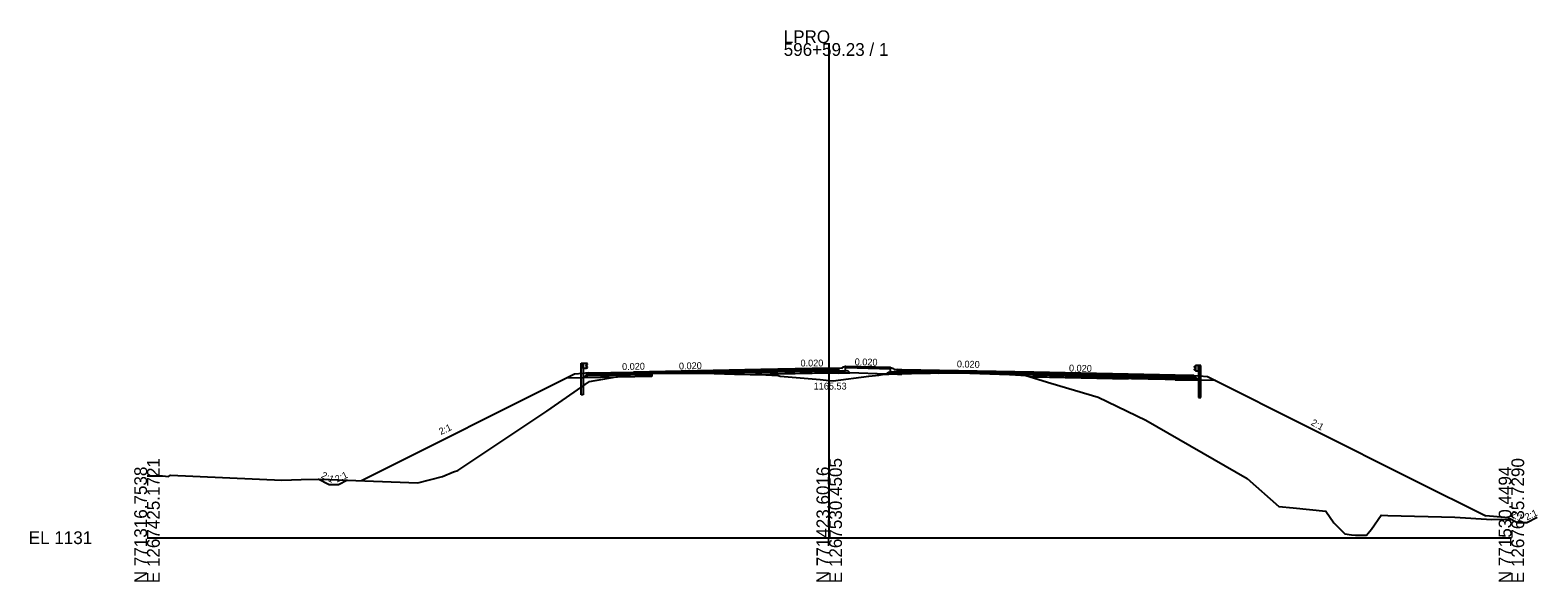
# Model space of a CAD drawing. Extents: x -3833 to 1267678, y -522 to 773248.
# Drawn here: x 4274.3 to 4605.8, y -9.7 to 111.5 of the extents above; entities that cross this region are included whole.
import ezdxf

# ---------------------------------------------------------------- set-up
doc = ezdxf.new("R2010")
doc.units = 0
for name, color, linetype in [('Exist Utilities Water UG Line SUE LOS B', 7, 'Continuous'), ('Prop Drainage Structure Catch Basin Grate 840 03E CELL', 7, 'Continuous'), ('Prop Drainage Structure Catch Basin Grate 840 03E Label', 7, 'Continuous'), ('Prop Drainage Structure Catch Basin Grate 840 03F CELL', 7, 'Continuous'), ('Prop Drainage Structure Catch Basin Grate 840 03F Label', 7, 'Continuous'), ('Prop Drainage Structure Catch Basin Grate 840 03G CELL', 7, 'Continuous'), ('Prop Drainage Structure Catch Basin Grate 840 03G Label', 7, 'Continuous'), ('Prop Drainage Structure Drop Inlet Grate 2 Narrow Slots and Flat Grates 840 29 CELL', 7, 'Continuous'), ('Prop Drainage Structure Drop Inlet Grate 2 Narrow Slots and Flat Grates 840 29 Label', 7, 'Continuous'), ('Prop Drainage Structure Headwall CELL', 7, 'Continuous'), ('Prop Drainage Structure Junction Box with Manhole CELL', 7, 'Continuous'), ('Prop Drainage Structure Junction Box with Manhole Label', 7, 'Continuous'), ('Prop Drainage Structure Junction Box with Manhole TB Label', 7, 'Continuous'), ('Prop Drainage Structure Pipe RCP 18in Class III', 7, 'Continuous'), ('Prop Drainage Structure Pipe RCP 18in Class III Label', 7, 'Continuous'), ('Prop Drainage Structure Pipe Removal', 7, 'Continuous'), ('Prop Drainage Structure Removal Label', 7, 'Continuous'), ('Prop Earthen Structure Ditch Flow Line', 7, 'Continuous'), ('Scratch_Level_3', 7, 'Continuous')]:
    doc.layers.add(name, color=color, linetype=linetype)

msp = doc.modelspace()

# ---------------------------------------------------------------- linework, layer by layer
at = {"layer": 'Prop Drainage Structure Catch Basin Grate 840 03F CELL'}
for p, q in [((4453.59, 37.62), (4453.68, 37.62)), ((4453.68, 37.62), (4463.49, 37.36)), ((4463.49, 37.36), (4463.49, 37.36)), ((4394, 35.93), (4347.15, 12.5)), ((4395.81, 36.07), (4394, 35.93)), ((4397, 36.17), (4395.81, 36.07)), ((4530.14, 35.63), (4531.33, 35.53)), ((4531.33, 35.53), (4533.14, 35.39)), ((4533.14, 35.39), (4578.79, 12.56)), ((4340.08, 11.62), (4337.63, 12.84)), ((4342.08, 11.62), (4340.08, 11.62)), ((4344.08, 12.62), (4342.08, 11.62)), ((4578.79, 12.56), (4594.36, 4.78)), ((4599.36, 4.36), (4594.36, 4.78)), ((4599.36, 4.36), (4601.36, 3.36)), ((4601.36, 3.36), (4603.36, 3.36)), ((4603.36, 3.36), (4605.65, 4.51))]:
    msp.add_line(p, q, dxfattribs=at)
at = {"layer": 'Prop Drainage Structure Catch Basin Grate 840 03F Label'}
for p, q in [((4435, 36.68), (4422.56, 36.43)), ((4435, 36.35), (4435, 36.68)), ((4435, 36.68), (4435, 36.68)), ((4465.98, 36.31), (4465.98, 36.64)), ((4465.98, 36.64), (4465.98, 36.64)), ((4465.98, 36.64), (4465.98, 36.64)), ((4465.98, 36.64), (4474.31, 36.49)), ((4474.31, 36.49), (4474.31, 36.49)), ((4474.31, 36.49), (4476.65, 36.45)), ((4396.4, 35.57), (4396.74, 35.91)), ((4407, 35.79), (4396.4, 35.57)), ((4396.4, 35.57), (4396.4, 35.57)), ((4396.4, 35.57), (4396.4, 35.57)), ((4396.74, 35.91), (4407, 36.12)), ((4396.74, 35.91), (4396.74, 35.91)), ((4411, 36.2), (4407, 36.12)), ((4407, 36.04), (4410.94, 36.18)), ((4407, 36.12), (4407, 35.79)), ((4407, 36.12), (4407, 36.04)), ((4407, 36.04), (4407, 36.04)), ((4407, 35.79), (4407, 35.79)), ((4410.94, 36.18), (4412, 36.18)), ((4412, 36.22), (4411, 36.2)), ((4422.56, 36.43), (4412, 36.22)), ((4412, 36.22), (4412, 36.22)), ((4412, 36.18), (4412, 36.18)), ((4412, 36.18), (4422.56, 36.17)), ((4422.56, 36.43), (4422.56, 36.43)), ((4422.56, 36.43), (4422.56, 36.43)), ((4422.56, 36.17), (4422.56, 36.17)), ((4422.56, 36.17), (4422.56, 36.17)), ((4422.56, 36.17), (4424.14, 36.13)), ((4424.14, 36.13), (4435, 36.35)), ((4424.14, 36.13), (4424.14, 36.13)), ((4424.14, 36.13), (4424.14, 36.13)), ((4435, 36.35), (4435, 36.35)), ((4474.11, 36.16), (4465.98, 36.31)), ((4465.98, 36.31), (4465.98, 36.31)), ((4465.98, 36.31), (4465.98, 36.31)), ((4465.98, 36.31), (4465.98, 36.31)), ((4465.98, 36.31), (4465.98, 36.31)), ((4474.31, 36.17), (4474.11, 36.16)), ((4476.65, 36.2), (4474.31, 36.17)), ((4474.31, 36.17), (4474.31, 36.17)), ((4476.65, 36.45), (4476.65, 36.45)), ((4476.65, 36.45), (4487.22, 36.23)), ((4487.22, 35.93), (4476.65, 36.2)), ((4476.65, 36.2), (4476.65, 36.2)), ((4487.22, 36.23), (4487.22, 36.23)), ((4487.22, 36.23), (4489.65, 36.19)), ((4489.65, 35.86), (4487.22, 35.93)), ((4487.22, 35.93), (4487.22, 35.93)), ((4489.65, 36.19), (4489.65, 36.19)), ((4489.65, 36.19), (4489.65, 36.19)), ((4489.65, 36.19), (4490.53, 36.17)), ((4489.85, 35.85), (4489.65, 35.86)), ((4489.65, 35.86), (4489.65, 35.86)), ((4489.65, 35.86), (4489.65, 35.86)), ((4490.53, 35.83), (4489.85, 35.85)), ((4489.85, 35.85), (4489.85, 35.85)), ((4490.53, 36.17), (4490.53, 36.17)), ((4490.53, 36.17), (4493.21, 36.11)), ((4493.21, 35.78), (4490.53, 35.83)), ((4490.53, 35.83), (4490.53, 35.83)), ((4493.21, 36.11), (4495, 36.08)), ((4495, 35.75), (4493.21, 35.78)), ((4495, 36.08), (4495, 36.08)), ((4495, 36.08), (4495, 35.75)), ((4495, 35.75), (4495, 35.75)), ((4495, 35.75), (4495, 35.75)), ((4526.06, 35.46), (4526.06, 35.13)), ((4530.39, 35.37), (4526.06, 35.46)), ((4526.06, 35.13), (4530.73, 35.03)), ((4530.73, 35.03), (4530.39, 35.37))]:
    msp.add_line(p, q, dxfattribs=at)
at = {"layer": 'Prop Drainage Structure Catch Basin Grate 840 03G CELL'}
for p, q in [((4395.94, 35.11), (4396.4, 35.57)), ((4411.01, 35.37), (4395.94, 35.11)), ((4396.4, 35.57), (4396.9, 35.58)), ((4396.9, 35.58), (4411, 35.87)), ((4526.06, 35.13), (4526.06, 34.67)), ((4530.23, 35.04), (4526.06, 35.13)), ((4526.06, 34.67), (4531.2, 34.57)), ((4530.73, 35.03), (4530.23, 35.04)), ((4531.2, 34.57), (4530.73, 35.03))]:
    msp.add_line(p, q, dxfattribs=at)
at = {"layer": 'Prop Drainage Structure Catch Basin Grate 840 03G Label'}
for p, q in [((4435, 36.93), (4435, 36.68)), ((4411, 36.45), (4411, 36.2)), ((4515.7, 35.91), (4515.7, 35.66))]:
    msp.add_line(p, q, dxfattribs=at)
at = {"layer": 'Prop Drainage Structure Drop Inlet Grate 2 Narrow Slots and Flat Grates 840 29 CELL'}
for p, q in [((4450, 0), (4450, 108.61)), ((4300, 0), (4450, 0)), ((4450, 0), (4600, 0))]:
    msp.add_line(p, q, dxfattribs=at)
at = {"layer": 'Prop Drainage Structure Drop Inlet Grate 2 Narrow Slots and Flat Grates 840 29 Label'}
msp.add_lwpolyline([(4300, 13.57), (4303.41, 13.58), (4304.74, 13.44), (4305.17, 13.74), (4329.66, 12.63), (4333.92, 12.74), (4338.12, 12.86), (4359.56, 12.01), (4364.96, 13.42), (4367.41, 14.46), (4368.35, 14.77), (4387.9, 27.75), (4397.33, 34.31), (4403.17, 35.33), (4406.53, 35.97), (4408.51, 36.04), (4410.92, 36.14), (4416.32, 36.14), (4422.5, 36.13), (4429.15, 35.94), (4436.09, 35.75), (4437.42, 35.67), (4438.81, 35.6), (4439.19, 35.5), (4448, 34.73), (4450, 34.53), (4450.85, 34.45), (4458.71, 35.45), (4460.88, 35.7), (4461.7, 35.87), (4464.48, 35.99), (4465.41, 36.03), (4468.12, 36.07), (4476.52, 36.2), (4480.93, 36.1), (4489.64, 35.87), (4491.45, 35.74), (4493.21, 35.62), (4498.74, 33.95), (4509.11, 30.83), (4519.64, 25.84), (4541.9, 13.01), (4548.89, 6.87), (4552.02, 6.57), (4559.22, 5.85), (4560.95, 3.23), (4563.36, 0.84), (4564.87, 0.62), (4565.69, 0.53), (4567.59, 0.57), (4568.17, 0.57), (4569.22, 1.89), (4571.35, 4.94), (4572.8, 4.84), (4587.56, 4.48), (4595.71, 3.96), (4597.72, 4.03), (4600, 3.97)], dxfattribs=at)
at = {"layer": 'Prop Drainage Structure Headwall CELL'}
for p, q in [((4450, 37.23), (4435, 36.93)), ((4435, 36.68), (4450, 36.98)), ((4435, 36.93), (4435, 36.93)), ((4435, 36.93), (4435, 36.68)), ((4435, 36.68), (4435, 36.68)), ((4435, 36.68), (4435, 36.68)), ((4452.09, 37.17), (4450, 37.23)), ((4450, 36.98), (4452.09, 36.92)), ((4452.09, 36.92), (4452.09, 37.17)), ((4452.09, 37.17), (4452.09, 37.17)), ((4452.09, 36.92), (4452.09, 36.92)), ((4452.09, 36.92), (4452.09, 36.92)), ((4464.99, 36.91), (4464.99, 36.66)), ((4465.98, 36.89), (4464.99, 36.91)), ((4464.99, 36.66), (4465.98, 36.64)), ((4465.98, 36.64), (4465.98, 36.89)), ((4465.98, 36.89), (4465.98, 36.89)), ((4396.74, 35.91), (4397, 36.17)), ((4407, 36.12), (4396.74, 35.91)), ((4396.74, 35.91), (4396.74, 35.91)), ((4396.74, 35.91), (4396.74, 35.91)), ((4397, 36.17), (4407, 36.37)), ((4397, 36.17), (4397, 36.17)), ((4407, 36.37), (4407, 36.12)), ((4407, 36.12), (4407, 36.12)), ((4526.06, 35.71), (4526.06, 35.46)), ((4530.14, 35.63), (4526.06, 35.71)), ((4526.06, 35.46), (4530.39, 35.37)), ((4530.39, 35.37), (4530.14, 35.63))]:
    msp.add_line(p, q, dxfattribs=at)
at = {"layer": 'Prop Drainage Structure Junction Box with Manhole CELL'}
for p, q in [((4450, 36.65), (4435, 36.35)), ((4452.09, 36.59), (4450, 36.65)), ((4452.08, 36.13), (4452.09, 36.59)), ((4452.09, 36.59), (4452.08, 36.13)), ((4454.09, 36.63), (4452.09, 36.59)), ((4452.09, 36.59), (4452.09, 36.59)), ((4452.09, 36.59), (4452.09, 36.59)), ((4454.51, 36.17), (4454.09, 36.63)), ((4433.82, 36.32), (4424.14, 36.13)), ((4424.14, 36.13), (4424.14, 36.13)), ((4424.14, 36.13), (4424.14, 36.13)), ((4424.14, 36.13), (4426.71, 36.06)), ((4426.71, 36.06), (4426.71, 36.06)), ((4426.71, 36.06), (4428.21, 36.01)), ((4426.71, 36.06), (4426.71, 36.06)), ((4428.21, 36.01), (4433.82, 35.86)), ((4435, 36.35), (4433.82, 36.32)), ((4433.82, 35.86), (4435.01, 35.89)), ((4435, 36.35), (4435, 36.35)), ((4435, 36.35), (4435, 36.35)), ((4435, 36.35), (4435.01, 35.89)), ((4435.01, 35.89), (4435, 36.35)), ((4435, 36.35), (4435, 36.35)), ((4435, 36.35), (4435, 36.35)), ((4435.01, 35.89), (4450, 36.19)), ((4435.01, 35.89), (4435.01, 35.89)), ((4435.01, 35.89), (4435.01, 35.89)), ((4435.01, 35.89), (4435.01, 35.89)), ((4435.01, 35.89), (4435.01, 35.89)), ((4435.01, 35.89), (4435.01, 35.89)), ((4450, 36.19), (4452.08, 36.13)), ((4452.08, 36.13), (4454.51, 36.17)), ((4452.08, 36.13), (4452.08, 36.13)), ((4452.08, 36.13), (4452.08, 36.13)), ((4452.08, 36.13), (4452.08, 36.13)), ((4452.08, 36.13), (4452.08, 36.13)), ((4462.54, 35.94), (4462.99, 36.37)), ((4464.99, 35.87), (4462.54, 35.94)), ((4462.54, 35.94), (4462.54, 35.94)), ((4462.99, 36.37), (4464.99, 36.33)), ((4464.99, 35.87), (4464.99, 36.33)), ((4464.99, 36.33), (4465.98, 36.31)), ((4464.99, 36.33), (4464.99, 35.87)), ((4465.98, 35.85), (4464.99, 35.87)), ((4465.98, 36.31), (4465.98, 35.85)), ((4465.98, 36.04), (4465.98, 36.31)), ((4465.98, 36.31), (4466.97, 36.29)), ((4467.69, 36.06), (4465.98, 36.04)), ((4466.97, 36.29), (4474.11, 36.16)), ((4474.11, 36.16), (4467.69, 36.06)), ((4493.76, 35.77), (4489.89, 35.85)), ((4489.89, 35.85), (4493.21, 35.62)), ((4493.21, 35.62), (4494.26, 35.3)), ((4495, 35.75), (4493.76, 35.77)), ((4494.26, 35.3), (4495, 35.29)), ((4495, 35.75), (4495, 35.29)), ((4515.7, 35.33), (4495, 35.75)), ((4495, 35.29), (4495, 35.75)), ((4495, 35.29), (4515.7, 34.88)), ((4515.7, 34.88), (4515.7, 35.33))]:
    msp.add_line(p, q, dxfattribs=at)
at = {"layer": 'Prop Drainage Structure Junction Box with Manhole Label'}
for p, q in [((4450, 36.98), (4435, 36.68)), ((4435, 36.68), (4435, 36.68)), ((4435, 36.68), (4435, 36.35)), ((4435, 36.35), (4450, 36.65)), ((4452.09, 36.92), (4450, 36.98)), ((4450, 36.65), (4452.09, 36.59)), ((4452.09, 36.59), (4452.09, 36.92)), ((4452.09, 36.92), (4452.09, 36.92)), ((4452.09, 36.59), (4452.09, 36.59)), ((4452.09, 36.59), (4452.09, 36.59)), ((4452.09, 36.59), (4452.09, 36.59)), ((4464.99, 36.66), (4464.99, 36.33)), ((4465.98, 36.64), (4464.99, 36.66)), ((4465.98, 36.31), (4465.98, 36.64)), ((4465.98, 36.64), (4465.98, 36.64)), ((4435, 36.35), (4435, 36.35)), ((4435, 36.35), (4435, 36.35)), ((4435, 36.35), (4435, 36.35)), ((4464.99, 36.33), (4465.98, 36.31)), ((4465.98, 36.31), (4465.98, 36.31)), ((4495, 36.08), (4495, 35.75)), ((4515.7, 35.66), (4495, 36.08)), ((4495, 35.75), (4515.7, 35.33)), ((4526.06, 35.46), (4515.7, 35.66)), ((4515.7, 35.33), (4519.01, 35.26)), ((4519.01, 35.26), (4526.06, 35.13)), ((4526.06, 35.13), (4526.06, 35.46))]:
    msp.add_line(p, q, dxfattribs=at)
at = {"layer": 'Prop Drainage Structure Junction Box with Manhole TB Label'}
for p, q in [((4395.94, 35.11), (4392.15, 35)), ((4411.01, 35.37), (4395.94, 35.11)), ((4411, 36.18), (4411.01, 35.37)), ((4450, 36.19), (4433.82, 35.86)), ((4452.08, 36.13), (4450, 36.19)), ((4454.51, 36.17), (4452.08, 36.13)), ((4462.54, 35.94), (4454.51, 36.17)), ((4464.99, 35.87), (4462.54, 35.94)), ((4465.98, 35.85), (4464.99, 35.87)), ((4465.98, 36.04), (4465.98, 35.85)), ((4534.92, 34.49), (4494.26, 35.3))]:
    msp.add_line(p, q, dxfattribs=at)
at = {"layer": 'Prop Drainage Structure Pipe RCP 18in Class III'}
for p, q in [((4395.43, 35.86), (4395.43, 38.36)), ((4395.43, 38.36), (4395.91, 38.36)), ((4395.91, 38.36), (4395.91, 35.85)), ((4395.91, 37.18), (4395.91, 38.36)), ((4395.91, 38.36), (4396.58, 38.36)), ((4396.58, 37.18), (4395.91, 37.18)), ((4396.58, 38.36), (4396.58, 37.18)), ((4396.58, 38.28), (4396.58, 37.26)), ((4396.68, 38.26), (4396.58, 38.28)), ((4396.58, 37.26), (4396.68, 37.28)), ((4396.59, 37.81), (4396.82, 38.01)), ((4396.59, 37.72), (4396.59, 37.81)), ((4396.82, 37.52), (4396.59, 37.72)), ((4396.82, 38.16), (4396.68, 38.26)), ((4396.68, 37.28), (4396.82, 37.38)), ((4396.82, 38.01), (4396.82, 38.16)), ((4396.82, 37.38), (4396.82, 37.52)), ((4530.3, 37.62), (4530.44, 37.72)), ((4530.3, 37.47), (4530.3, 37.62)), ((4530.3, 37.62), (4530.3, 37.62)), ((4530.53, 37.27), (4530.3, 37.47)), ((4530.3, 37.47), (4530.3, 37.47)), ((4530.3, 37.47), (4530.3, 37.47)), ((4530.3, 36.98), (4530.53, 37.18)), ((4530.3, 36.84), (4530.3, 36.98)), ((4530.3, 36.98), (4530.3, 36.98)), ((4530.44, 36.74), (4530.3, 36.84)), ((4530.3, 36.84), (4530.3, 36.84)), ((4530.3, 36.84), (4530.3, 36.84)), ((4530.44, 37.72), (4530.54, 37.74)), ((4530.44, 37.72), (4530.44, 37.72)), ((4530.54, 36.71), (4530.44, 36.74)), ((4530.44, 36.74), (4530.44, 36.74)), ((4530.53, 37.18), (4530.53, 37.27)), ((4530.53, 37.18), (4530.53, 37.18)), ((4530.54, 37.82), (4530.54, 36.63)), ((4531.21, 37.82), (4530.54, 37.82)), ((4530.54, 37.74), (4530.54, 36.71)), ((4530.54, 36.71), (4530.54, 36.71)), ((4530.54, 36.63), (4531.21, 36.63)), ((4531.21, 36.63), (4531.21, 37.82)), ((4531.21, 37.82), (4531.21, 35.31)), ((4531.7, 37.82), (4531.21, 37.82)), ((4531.7, 35.32), (4531.7, 37.82)), ((4395.43, 31.35), (4395.43, 35.86)), ((4395.91, 35.85), (4395.91, 31.35)), ((4531.21, 35.31), (4531.21, 30.81)), ((4531.7, 30.81), (4531.7, 35.32)), ((4395.91, 31.35), (4395.43, 31.35)), ((4531.21, 30.81), (4531.7, 30.81))]:
    msp.add_line(p, q, dxfattribs=at)
at = {"layer": 'Prop Drainage Structure Pipe Removal'}
for p, q in [((4453.68, 37.62), (4453.59, 37.62)), ((4453.59, 37.62), (4453.59, 37.37)), ((4453.59, 37.37), (4453.68, 37.37)), ((4463.49, 37.36), (4453.68, 37.62)), ((4453.68, 37.37), (4463.49, 37.11)), ((4463.49, 37.11), (4463.49, 37.36)), ((4463.49, 37.36), (4463.49, 37.36)), ((4463.49, 37.11), (4463.49, 37.11))]:
    msp.add_line(p, q, dxfattribs=at)
at = {"layer": 'Prop Drainage Structure Removal Label'}
for p, q in [((4452.78, 37.19), (4452.09, 37.17)), ((4452.09, 36.59), (4452.09, 37.17)), ((4452.09, 36.59), (4453.59, 36.62)), ((4452.84, 37.26), (4452.84, 37.25)), ((4453.59, 37.62), (4452.94, 37.4)), ((4453.59, 36.62), (4453.59, 37.62)), ((4463.49, 36.36), (4463.49, 37.36)), ((4463.49, 37.36), (4464.14, 37.14)), ((4464.24, 37.01), (4464.24, 36.99)), ((4464.3, 36.93), (4464.99, 36.91)), ((4464.99, 36.33), (4464.99, 36.91)), ((4464.99, 36.33), (4463.49, 36.36))]:
    msp.add_line(p, q, dxfattribs=at)
for centre, radius, start, end in [((4452.78, 37.25), 0.0625, 271.1458, 360), ((4452.98, 37.26), 0.146, 108.435, 180), ((4464.09, 37.01), 0.146, 0, 71.565), ((4464.3, 36.99), 0.0625, 180, 268.8542)]:
    msp.add_arc(centre, radius, start, end, dxfattribs=at)
at = {"layer": 'Prop Earthen Structure Ditch Flow Line'}
for p, q in [((4435, 36.93), (4407, 36.37)), ((4407, 36.12), (4435, 36.68)), ((4435, 36.68), (4435, 36.93)), ((4435, 36.68), (4435, 36.68)), ((4495, 36.33), (4465.98, 36.89)), ((4465.98, 36.89), (4465.98, 36.64)), ((4465.98, 36.64), (4465.98, 36.64)), ((4465.98, 36.64), (4495, 36.08)), ((4407, 36.37), (4407, 36.37)), ((4407, 36.37), (4407, 36.12)), ((4407, 36.12), (4411, 36.2)), ((4407, 36.12), (4407, 36.12)), ((4495, 36.08), (4495, 36.33)), ((4495, 36.33), (4495, 36.33)), ((4495, 36.33), (4495, 36.08)), ((4526.06, 35.71), (4495, 36.33)), ((4495, 36.08), (4495, 36.08)), ((4495, 36.08), (4495, 36.08)), ((4495, 36.08), (4515.7, 35.66)), ((4515.7, 35.66), (4516.52, 35.64)), ((4516.52, 35.64), (4526.06, 35.46)), ((4526.06, 35.46), (4526.06, 35.71))]:
    msp.add_line(p, q, dxfattribs=at)

# ---------------------------------------------------------------- texts
at = {"layer": 'Exist Utilities Water UG Line SUE LOS B'}
for rotation, p in [(1.397, (4404.47, 36.8)), (1.397, (4416.98, 36.93)), (0.2693, (4443.69, 37.59)), (358.8542, (4455.59, 37.88)), (358.8542, (4478.06, 37.4)), (358.8542, (4502.71, 36.5))]:
    msp.add_text('0.020', height=1.5, rotation=rotation, dxfattribs=at).set_placement(p)
at = {"layer": 'Prop Drainage Structure Catch Basin Grate 840 03E CELL'}
msp.add_text('1165.53', height=1.5, dxfattribs=at).set_placement((4446.58, 32.53))
at = {"layer": 'Prop Drainage Structure Catch Basin Grate 840 03E Label'}
for p in [(4435, 36.93), (4435, 36.93), (4450, 37.23), (4464.25, 36.94), (4465, 36.93), (4465, 36.93), (4401, 36.25), (4411, 36.45), (4411, 36.45), (4515.7, 35.91), (4519.77, 35.83), (4524.97, 35.42), (4526.77, 35.27), (4344.08, 12.62)]:
    msp.add_text('X', height=0.00025, dxfattribs=at).set_placement(p)
at = {"layer": 'Prop Drainage Structure Drop Inlet Grate 2 Narrow Slots and Flat Grates 840 29 CELL'}
for s, p in [('LPRO', (4440, 108.61)), ('596+59.23 / 1', (4440, 105.81)), ('EL 1131', (4274, -1.4))]:
    msp.add_text(s, height=2.8, dxfattribs=at).set_placement(p)
for s, p in [('E 1267425.1721', (4302.8, -10)), ('E 1267530.4505', (4452.8, -10)), ('E 1267635.7290', (4602.8, -10)), ('N 771316.7538', (4300, -10)), ('N 771423.6016', (4450, -10)), ('N 771530.4494', (4600, -10))]:
    msp.add_text(s, height=2.8, rotation=90, dxfattribs=at).set_placement(p)
at = {"layer": 'Prop Drainage Structure Pipe RCP 18in Class III Label'}
msp.add_text('2:1', height=1.5, rotation=330.6954, dxfattribs=at).set_placement((4555.79, 24.84))
at = {"layer": 'Scratch_Level_3'}
for rotation, p in [(24.9367, (4364.6, 22.53)), (335.0633, (4338.16, 13.2)), (24.9367, (4341.78, 12.09)), (335.0633, (4599.61, 4.66)), (24.9367, (4603.37, 3.77))]:
    msp.add_text('2:1', height=1.5, rotation=rotation, dxfattribs=at).set_placement(p)

doc.saveas('drawing.dxf')
